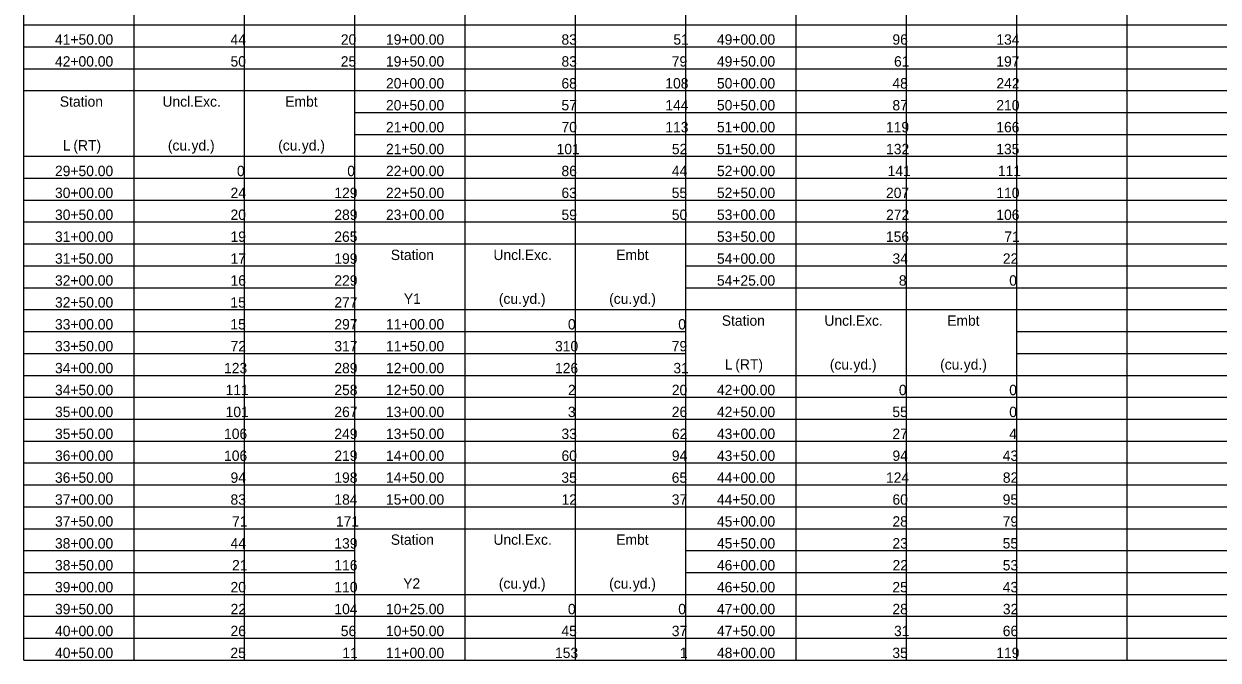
# Model space of a CAD drawing. Extents: x 239 to 408, y 686 to 906.
# Drawn here: x 256.1 to 346.3, y 686 to 734.1 of the extents above; entities that cross this region are included whole.
import ezdxf

# ---------------------------------------------------------------- set-up
doc = ezdxf.new("R2010")
doc.units = 0
doc.layers.add('Default', color=7, linetype='Continuous')

msp = doc.modelspace()

# ---------------------------------------------------------------- linework, layer by layer
at = {"layer": 'Default'}
for p, q in [((256.088, 686.039), (256.088, 778.659)), ((264.421, 730.695), (264.421, 778.659)), ((272.755, 730.695), (272.755, 778.659)), ((281.088, 686.039), (281.088, 778.659)), ((331.088, 714.156), (331.088, 778.659)), ((272.755, 730.695), (272.755, 773.697)), ((306.088, 714.156), (306.088, 762.12)), ((314.421, 714.156), (314.421, 762.12)), ((322.754, 714.156), (322.754, 762.12)), ((331.088, 714.156), (331.088, 752.196)), ((339.421, 686.039), (339.421, 752.196)), ((339.421, 686.039), (339.421, 752.196)), ((289.421, 719.118), (289.421, 743.927)), ((297.755, 719.118), (297.755, 743.927)), ((306.088, 719.118), (306.088, 743.927)), ((256.088, 734.003), (331.088, 734.003)), ((331.088, 734.003), (406.087, 734.003)), ((256.088, 732.349), (331.088, 732.349)), ((331.088, 732.349), (406.087, 732.349)), ((256.088, 730.695), (281.088, 730.695)), ((256.088, 730.695), (272.755, 730.695)), ((264.421, 729.041), (264.421, 730.695)), ((272.755, 730.695), (331.088, 730.695)), ((272.755, 729.041), (272.755, 730.695)), ((272.755, 729.041), (272.755, 730.695)), ((281.088, 729.041), (281.088, 730.695)), ((331.088, 730.695), (406.087, 730.695)), ((256.088, 729.041), (331.088, 729.041)), ((256.088, 729.041), (281.088, 729.041)), ((264.421, 686.039), (264.421, 729.041)), ((264.421, 724.079), (264.421, 729.041)), ((272.755, 686.039), (272.755, 729.041)), ((272.755, 724.079), (272.755, 729.041)), ((331.088, 729.041), (406.087, 729.041)), ((281.088, 727.387), (331.088, 727.387)), ((331.088, 727.387), (406.087, 727.387)), ((281.088, 725.733), (331.088, 725.733)), ((331.088, 725.733), (406.087, 725.733)), ((256.088, 724.079), (331.088, 724.079)), ((256.088, 724.079), (281.088, 724.079)), ((272.755, 686.039), (272.755, 724.079)), ((331.088, 724.079), (406.087, 724.079)), ((256.088, 722.425), (339.421, 722.425)), ((331.088, 722.425), (406.087, 722.425)), ((256.088, 720.771), (331.088, 720.771)), ((331.088, 720.771), (406.087, 720.771)), ((256.088, 719.118), (331.088, 719.118)), ((281.088, 719.118), (306.088, 719.118)), ((281.088, 717.464), (281.088, 719.118)), ((289.421, 717.464), (289.421, 719.118)), ((297.755, 717.464), (297.755, 719.118)), ((306.088, 719.118), (331.088, 719.118)), ((306.088, 717.464), (306.088, 719.118)), ((331.088, 719.118), (406.087, 719.118)), ((256.088, 717.464), (331.088, 717.464)), ((281.088, 717.464), (306.088, 717.464)), ((289.421, 697.616), (289.421, 717.464)), ((289.421, 712.502), (289.421, 717.464)), ((297.755, 697.616), (297.755, 717.464)), ((297.755, 712.502), (297.755, 717.464)), ((306.088, 697.616), (306.088, 717.464)), ((331.088, 717.464), (406.087, 717.464)), ((256.088, 715.81), (281.088, 715.81)), ((306.088, 715.81), (331.088, 715.81)), ((331.088, 715.81), (406.087, 715.81)), ((256.088, 714.156), (281.088, 714.156)), ((306.088, 714.156), (331.088, 714.156)), ((306.088, 714.156), (331.088, 714.156)), ((306.088, 712.502), (306.088, 714.156)), ((314.421, 712.502), (314.421, 714.156)), ((322.754, 712.502), (322.754, 714.156)), ((331.088, 714.156), (406.087, 714.156)), ((331.088, 712.502), (331.088, 714.156)), ((256.088, 712.502), (331.088, 712.502)), ((281.088, 712.502), (331.088, 712.502)), ((306.088, 686.039), (306.088, 712.502)), ((314.421, 686.039), (314.421, 712.502)), ((314.421, 707.54), (314.421, 712.502)), ((322.754, 686.039), (322.754, 712.502)), ((322.754, 707.54), (322.754, 712.502)), ((331.088, 712.502), (406.087, 712.502)), ((331.088, 686.039), (331.088, 712.502)), ((331.088, 686.039), (331.088, 712.502)), ((256.088, 710.848), (306.088, 710.848)), ((331.088, 710.848), (406.087, 710.848)), ((256.088, 709.194), (306.088, 709.194)), ((331.088, 709.194), (406.087, 709.194)), ((256.088, 707.54), (331.088, 707.54)), ((306.088, 707.54), (331.088, 707.54)), ((331.088, 707.54), (406.087, 707.54)), ((256.088, 705.886), (331.088, 705.886)), ((331.088, 705.886), (406.087, 705.886)), ((256.088, 704.232), (331.088, 704.232)), ((331.088, 704.232), (406.087, 704.232)), ((256.088, 702.578), (331.088, 702.578)), ((331.088, 702.578), (406.087, 702.578)), ((256.088, 700.924), (331.088, 700.924)), ((331.088, 700.924), (406.087, 700.924)), ((256.088, 699.27), (331.088, 699.27)), ((331.088, 699.27), (406.087, 699.27)), ((256.088, 697.616), (331.088, 697.616)), ((281.088, 697.616), (306.088, 697.616)), ((281.088, 695.962), (281.088, 697.616)), ((289.421, 695.962), (289.421, 697.616)), ((297.755, 695.962), (297.755, 697.616)), ((306.088, 697.616), (331.088, 697.616)), ((306.088, 695.962), (306.088, 697.616)), ((331.088, 697.616), (406.087, 697.616)), ((256.088, 695.962), (331.088, 695.962)), ((281.088, 695.962), (306.088, 695.962)), ((289.421, 686.039), (289.421, 695.962)), ((289.421, 691.001), (289.421, 695.962)), ((297.755, 686.039), (297.755, 695.962)), ((297.755, 691.001), (297.755, 695.962)), ((306.088, 686.039), (306.088, 695.962)), ((331.088, 695.962), (406.087, 695.962)), ((256.088, 694.309), (281.088, 694.309)), ((306.088, 694.309), (331.088, 694.309)), ((331.088, 694.309), (406.087, 694.309)), ((256.088, 692.655), (281.088, 692.655)), ((306.088, 692.655), (331.088, 692.655)), ((331.088, 692.655), (406.087, 692.655)), ((256.088, 691.001), (331.088, 691.001)), ((281.088, 691.001), (306.088, 691.001)), ((331.088, 691.001), (406.087, 691.001)), ((256.088, 689.347), (331.088, 689.347)), ((331.088, 689.347), (406.087, 689.347)), ((256.088, 687.693), (331.088, 687.693)), ((331.088, 687.693), (406.087, 687.693)), ((256.088, 686.039), (406.087, 686.039))]:
    msp.add_line(p, q, dxfattribs=at)

# ---------------------------------------------------------------- texts
for s, height, p in [('41+50.00', 0.7829, (258.439, 732.506)), ('44', 0.7829, (271.697, 732.506)), ('20', 0.7829, (280.03, 732.506)), ('19+00.00', 0.7829, (283.439, 732.506)), ('83', 0.7829, (296.694, 732.506)), ('51', 0.7829, (305.149, 732.506)), ('49+00.00', 0.7829, (308.439, 732.506)), ('96', 0.7829, (321.694, 732.506)), ('134', 0.7829, (329.544, 732.506)), ('42+00.00', 0.7829, (258.439, 730.852)), ('50', 0.7829, (271.697, 730.852)), ('25', 0.7829, (280.023, 730.852)), ('19+50.00', 0.7829, (283.439, 730.852)), ('83', 0.7829, (296.694, 730.852)), ('79', 0.7829, (305.026, 730.852)), ('49+50.00', 0.7829, (308.439, 730.852)), ('61', 0.7829, (321.815, 730.852)), ('197', 0.7829, (329.541, 730.852)), ('20+00.00', 0.7829, (283.439, 729.198)), ('68', 0.7829, (296.693, 729.198)), ('108', 0.7829, (304.54, 729.198)), ('50+00.00', 0.7829, (308.439, 729.198)), ('48', 0.7829, (321.693, 729.198)), ('242', 0.7829, (329.547, 729.198)), ('Station', 0.7829, (258.802, 727.823)), ('Uncl.', 0.7829, (266.557, 727.823)), (' Exc.', 0.7829, (268.636, 727.823)), ('Embt', 0.7829, (275.833, 727.823)), ('20+50.00', 0.7829, (283.439, 727.544)), ('57', 0.7829, (296.694, 727.544)), ('144', 0.7829, (304.544, 727.544)), ('50+50.00', 0.7829, (308.439, 727.544)), ('87', 0.7829, (321.694, 727.544)), ('210', 0.7829, (329.543, 727.544)), ('21+00.00', 0.7829, (283.439, 725.89)), ('70', 0.7829, (296.696, 725.89)), ('113', 0.7829, (304.541, 725.89)), ('51+00.00', 0.7829, (308.439, 725.89)), ('119', 0.7829, (321.206, 725.89)), ('166', 0.7829, (329.541, 725.89)), ('L', 0.783, (259.027, 724.515)), (' (RT)', 0.7829, (259.536, 724.515)), ('(cu.', 0.7829, (266.964, 724.515)), (' yd.)', 0.7829, (268.459, 724.515)), ('(cu.', 0.7829, (275.297, 724.515)), (' yd.)', 0.7829, (276.792, 724.515)), ('21+50.00', 0.7829, (283.439, 724.236)), ('101', 0.7829, (296.329, 724.236)), ('52', 0.7829, (305.034, 724.236)), ('51+50.00', 0.7829, (308.439, 724.236)), ('132', 0.7829, (321.214, 724.236)), ('135', 0.7829, (329.536, 724.236)), ('29+50.00', 0.7829, (258.439, 722.582)), ('0', 0.783, (272.183, 722.582)), ('0', 0.783, (280.516, 722.582)), ('22+00.00', 0.7829, (283.439, 722.582)), ('86', 0.7829, (296.694, 722.582)), ('44', 0.7829, (305.03, 722.582)), ('52+00.00', 0.7829, (308.439, 722.582)), ('141', 0.7829, (321.329, 722.582)), ('111', 0.7829, (329.662, 722.582)), ('30+00.00', 0.7829, (258.439, 720.928)), ('24', 0.7829, (271.697, 720.928)), ('129', 0.7829, (279.54, 720.928)), ('22+50.00', 0.7829, (283.439, 720.928)), ('63', 0.7829, (296.694, 720.928)), ('55', 0.7829, (305.023, 720.928)), ('52+50.00', 0.7829, (308.439, 720.928)), ('207', 0.7829, (321.207, 720.928)), ('110', 0.7829, (329.543, 720.928)), ('30+50.00', 0.7829, (258.439, 719.274)), ('20', 0.7829, (271.697, 719.274)), ('289', 0.7829, (279.54, 719.274)), ('23+00.00', 0.7829, (283.439, 719.274)), ('59', 0.7829, (296.693, 719.274)), ('50', 0.7829, (305.03, 719.274)), ('53+00.00', 0.7829, (308.439, 719.274)), ('272', 0.7829, (321.214, 719.274)), ('106', 0.7829, (329.541, 719.274)), ('31+00.00', 0.7829, (258.439, 717.62)), ('19', 0.7829, (271.693, 717.62)), ('265', 0.7829, (279.536, 717.62)), ('53+50.00', 0.7829, (308.439, 717.62)), ('156', 0.7829, (321.207, 717.62)), ('71', 0.7829, (330.148, 717.62)), ('31+50.00', 0.7829, (258.439, 715.966)), ('17', 0.7829, (271.694, 715.966)), ('199', 0.7829, (279.54, 715.966)), ('Station', 0.7829, (283.802, 716.245)), ('Uncl.', 0.7829, (291.557, 716.245)), (' Exc.', 0.7829, (293.636, 716.245)), ('Embt', 0.7829, (300.833, 716.245)), ('54+00.00', 0.7829, (308.439, 715.966)), ('34', 0.7829, (321.697, 715.966)), ('22', 0.7829, (330.034, 715.966)), ('32+00.00', 0.7829, (258.439, 714.312)), ('16', 0.7829, (271.694, 714.312)), ('229', 0.7829, (279.54, 714.312)), ('54+25.00', 0.7829, (308.439, 714.312)), ('8', 0.783, (322.179, 714.312)), ('0', 0.783, (330.516, 714.312)), ('Y1', 0.7829, (284.79, 712.937)), ('(cu.', 0.7829, (291.964, 712.937)), (' yd.)', 0.7829, (293.459, 712.937)), ('(cu.', 0.7829, (300.297, 712.937)), (' yd.)', 0.7829, (301.792, 712.937)), ('32+50.00', 0.7829, (258.439, 712.658)), ('15', 0.7829, (271.689, 712.658)), ('277', 0.7829, (279.541, 712.658)), ('33+00.00', 0.7829, (258.439, 711.004)), ('15', 0.7829, (271.689, 711.004)), ('297', 0.7829, (279.541, 711.004)), ('11+00.00', 0.7829, (283.439, 711.004)), ('0', 0.783, (297.183, 711.004)), ('0', 0.783, (305.516, 711.004)), ('Station', 0.7829, (308.802, 711.283)), ('Uncl.', 0.7829, (316.557, 711.283)), (' Exc.', 0.7829, (318.636, 711.283)), ('Embt', 0.7829, (325.832, 711.283)), ('33+50.00', 0.7829, (258.439, 709.351)), ('72', 0.7829, (271.701, 709.351)), ('317', 0.7829, (279.541, 709.351)), ('11+50.00', 0.7829, (283.439, 709.351)), ('310', 0.7829, (296.21, 709.351)), ('79', 0.7829, (305.026, 709.351)), ('34+00.00', 0.7829, (258.439, 707.697)), ('123', 0.7829, (271.208, 707.697)), ('289', 0.7829, (279.54, 707.697)), ('12+00.00', 0.7829, (283.439, 707.697)), ('126', 0.7829, (296.208, 707.697)), ('31', 0.7829, (305.149, 707.697)), ('L', 0.783, (309.027, 707.976)), (' (RT)', 0.7829, (309.535, 707.976)), ('(cu.', 0.7829, (316.964, 707.976)), (' yd.)', 0.7829, (318.459, 707.976)), ('(cu.', 0.7829, (325.297, 707.976)), (' yd.)', 0.7829, (326.792, 707.976)), ('34+50.00', 0.7829, (258.439, 706.043)), ('111', 0.7829, (271.329, 706.043)), ('258', 0.7829, (279.54, 706.043)), ('12+50.00', 0.7829, (283.439, 706.043)), ('2', 0.783, (297.187, 706.043)), ('20', 0.7829, (305.03, 706.043)), ('42+00.00', 0.7829, (308.439, 706.043)), ('0', 0.783, (322.183, 706.043)), ('0', 0.783, (330.516, 706.043)), ('35+00.00', 0.7829, (258.439, 704.389)), ('101', 0.7829, (271.329, 704.389)), ('267', 0.7829, (279.541, 704.389)), ('13+00.00', 0.7829, (283.439, 704.389)), ('3', 0.783, (297.181, 704.389)), ('26', 0.7829, (305.027, 704.389)), ('42+50.00', 0.7829, (308.439, 704.389)), ('55', 0.7829, (321.689, 704.389)), ('0', 0.783, (330.516, 704.389)), ('35+50.00', 0.7829, (258.439, 702.735)), ('106', 0.7829, (271.208, 702.735)), ('249', 0.7829, (279.54, 702.735)), ('13+50.00', 0.7829, (283.439, 702.735)), ('33', 0.7829, (296.694, 702.735)), ('62', 0.7829, (305.034, 702.735)), ('43+00.00', 0.7829, (308.439, 702.735)), ('27', 0.7829, (321.694, 702.735)), ('4', 0.783, (330.517, 702.735)), ('36+00.00', 0.7829, (258.439, 701.081)), ('106', 0.7829, (271.208, 701.081)), ('219', 0.7829, (279.54, 701.081)), ('14+00.00', 0.7829, (283.439, 701.081)), ('60', 0.7829, (296.696, 701.081)), ('94', 0.7829, (305.03, 701.081)), ('43+50.00', 0.7829, (308.439, 701.081)), ('94', 0.7829, (321.697, 701.081)), ('43', 0.7829, (330.027, 701.081)), ('36+50.00', 0.7829, (258.439, 699.427)), ('94', 0.7829, (271.697, 699.427)), ('198', 0.7829, (279.54, 699.427)), ('14+50.00', 0.7829, (283.439, 699.427)), ('35', 0.7829, (296.689, 699.427)), ('65', 0.7829, (305.023, 699.427)), ('44+00.00', 0.7829, (308.439, 699.427)), ('124', 0.7829, (321.21, 699.427)), ('82', 0.7829, (330.034, 699.427)), ('37+00.00', 0.7829, (258.439, 697.773)), ('83', 0.7829, (271.694, 697.773)), ('184', 0.7829, (279.544, 697.773)), ('15+00.00', 0.7829, (283.439, 697.773)), ('12', 0.7829, (296.701, 697.773)), ('37', 0.7829, (305.027, 697.773)), ('44+50.00', 0.7829, (308.439, 697.773)), ('60', 0.7829, (321.696, 697.773)), ('95', 0.7829, (330.022, 697.773)), ('37+50.00', 0.7829, (258.439, 696.119)), ('71', 0.7829, (271.815, 696.119)), ('171', 0.7829, (279.662, 696.119)), ('45+00.00', 0.7829, (308.439, 696.119)), ('28', 0.7829, (321.693, 696.119)), ('79', 0.7829, (330.026, 696.119)), ('Station', 0.7829, (283.802, 694.744)), ('Uncl.', 0.7829, (291.557, 694.744)), (' Exc.', 0.7829, (293.636, 694.744)), ('Embt', 0.7829, (300.833, 694.744)), ('38+00.00', 0.7829, (258.439, 694.465)), ('44', 0.7829, (271.697, 694.465)), ('139', 0.7829, (279.54, 694.465)), ('45+50.00', 0.7829, (308.439, 694.465)), ('23', 0.7829, (321.694, 694.465)), ('55', 0.7829, (330.022, 694.465)), ('38+50.00', 0.7829, (258.439, 692.811)), ('21', 0.7829, (271.815, 692.811)), ('116', 0.7829, (279.541, 692.811)), ('46+00.00', 0.7829, (308.439, 692.811)), ('22', 0.7829, (321.701, 692.811)), ('53', 0.7829, (330.027, 692.811)), ('39+00.00', 0.7829, (258.439, 691.157)), ('20', 0.7829, (271.697, 691.157)), ('110', 0.7829, (279.543, 691.157)), ('Y2', 0.7829, (284.741, 691.436)), ('(cu.', 0.7829, (291.964, 691.436)), (' yd.)', 0.7829, (293.459, 691.436)), ('(cu.', 0.7829, (300.297, 691.436)), (' yd.)', 0.7829, (301.792, 691.436)), ('46+50.00', 0.7829, (308.439, 691.157)), ('25', 0.7829, (321.689, 691.157)), ('43', 0.7829, (330.027, 691.157)), ('39+50.00', 0.7829, (258.439, 689.503)), ('22', 0.7829, (271.701, 689.503)), ('104', 0.7829, (279.544, 689.503)), ('10+25.00', 0.7829, (283.439, 689.503)), ('0', 0.783, (297.183, 689.503)), ('0', 0.783, (305.516, 689.503)), ('47+00.00', 0.7829, (308.439, 689.503)), ('28', 0.7829, (321.693, 689.503)), ('32', 0.7829, (330.034, 689.503)), ('40+00.00', 0.7829, (258.439, 687.849)), ('26', 0.7829, (271.694, 687.849)), ('56', 0.7829, (280.027, 687.849)), ('10+50.00', 0.7829, (283.439, 687.849)), ('45', 0.7829, (296.689, 687.849)), ('37', 0.7829, (305.027, 687.849)), ('47+50.00', 0.7829, (308.439, 687.849)), ('31', 0.7829, (321.815, 687.849)), ('66', 0.7829, (330.027, 687.849)), ('40+50.00', 0.7829, (258.439, 686.195)), ('25', 0.7829, (271.689, 686.195)), ('11', 0.7829, (280.149, 686.195)), ('11+00.00', 0.7829, (283.439, 686.195)), ('153', 0.7829, (296.208, 686.195)), ('1', 0.783, (305.635, 686.195)), ('48+00.00', 0.7829, (308.439, 686.195)), ('35', 0.7829, (321.689, 686.195)), ('119', 0.7829, (329.54, 686.195))]:
    msp.add_text(s, height=height, dxfattribs=at).set_placement(p)

doc.saveas('drawing.dxf')
